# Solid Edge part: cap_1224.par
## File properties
Author: CADSoft
Template: Sync Iso Part.par
Last saved by: Cadcim
Revision: 9
Application: Solid Edge
Accuracy: 0.990
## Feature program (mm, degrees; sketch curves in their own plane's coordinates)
sketch for "Hole_1" plane through (0, 0, 47.9577) normal (0, 0, 1) x-axis (0, 1, 0)
  hole centre (0, 0) bore radius 3
hole "Hole_1" diameter 6 through
pattern "unnamed Pattern 1" of "Hole_1"
sketch for "Hole_2" plane through (-40.0381, 8.231, 36) normal (0, 0, 1) x-axis (1, 0, 0)
  hole centre (1.0381, -8.231) bore radius 6
hole "Hole_2" diameter 12 through
sketch for "unnamed Hole 1" plane through (38.3695, 10.2267, 36) normal (0, 0, 1) x-axis (1, 0, 0)
  hole centre (0.6305, -10.2267) bore radius 6
hole "unnamed Hole 1" through
pattern "unnamed Pattern 2" of "Hole_2", "unnamed Hole 1"
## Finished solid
Body 1: solid body, 21 faces, 50 edges, 28 vertices.
  Faces by surface: plane 11, cylinder 10
  Edges by curve: line 30, circle 16, intersection 4
Bounding box of the edges (mm): 108.000 x 46.000 x 40.000, from (-54, -23, 8) to (54, 23, 48).
Cylindrical faces by radius (mm): R3 x1, R4 x1, R6 x2, R17 x2, R24.3516 x1, R48 x1, R54 x2
Planar faces by outward normal: +x 1, +y 1, +z 3, -x 1, -y 1, -z 4
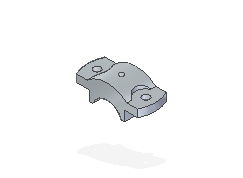
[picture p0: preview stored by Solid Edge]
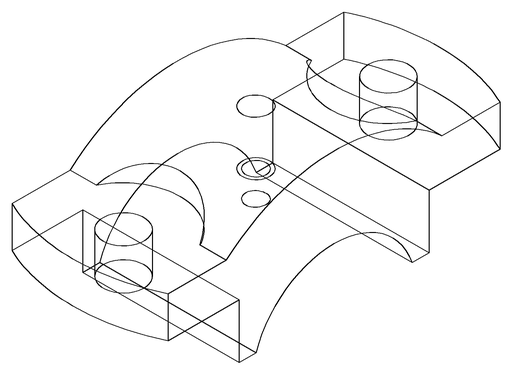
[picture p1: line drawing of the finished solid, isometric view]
